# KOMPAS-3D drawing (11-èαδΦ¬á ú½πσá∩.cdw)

Views: Вид 1
Referenced files in H:\#РИСХМ\Детали машин\Компас\Редуктор\: Крышка глухая ОКМА-30.06.01.00.15.cdw
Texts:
  Крышка
  Андрей
  ооо
  125 1 126 1 127 1 128 0 50 1|SPDS|125 1 126 1 127 1 128 0 50 1
  129 1 130 1 131 1 132 0 50 1|SPDS|129 1 130 1 131 1 132 0 50 1
  Ra3.2
  Ra6.3
  Уклоны формовочные по ГОСТ 3212-80.
  Необработанные внутренние поверхности покрыть грунтовкой.
  СЧ120ГОСТ 1412-85
  ТФ ДГТУ
  ОКМА-30.06.01.00.15-
Dimensions and other numbers on the sheet: 90; 140; 80; 40; 22; 1,5; 20; 0,02; 120; 4отв.; 13; 0,8; 4; 1:2; 1; 0,5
